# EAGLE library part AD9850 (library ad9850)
CMOS, 125 MHz Complete DDS Synthesizer
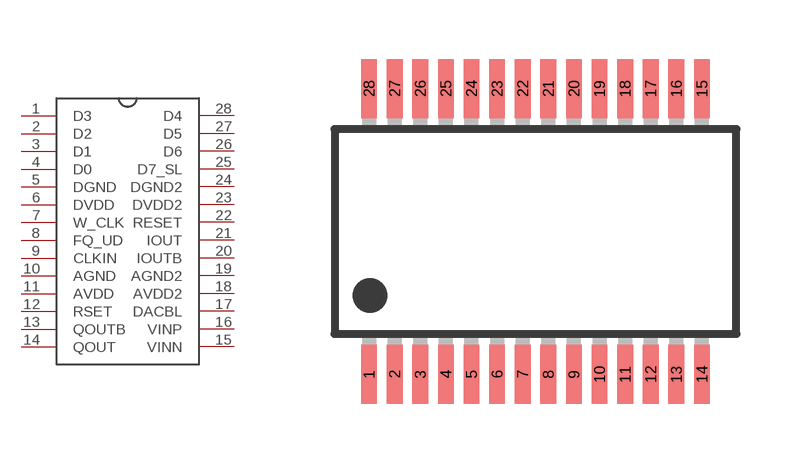
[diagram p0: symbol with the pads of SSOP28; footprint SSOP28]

Designator prefix -

## AD9850  [SSOP28]
1  D3  in
2  D2  in
3  D1  in
4  D0
5  DGND  sup
6  DVDD  sup
7  W_CLK
8  FQ_UD
9  CLKIN  in
10  AGND  sup
11  AVDD  sup
12  RSET  in
13  QOUTB  out
14  QOUT  out
15  VINN  in
16  VINP  in
17  DACBL  nc
18  AVDD2  sup
19  AGND2  sup
20  IOUTB  out
21  IOUT  out
22  RESET  in
23  DVDD2  sup
24  DGND2  sup
25  D7_SL  in
26  D6  in
27  D5  in
28  D4  in

## Footprint SSOP28 (pad centres in mm)
smd 0.4 x 1.5: 1 -4.225,-3.625; 2 -3.575,-3.625; 3 -2.925,-3.625; 4 -2.275,-3.625; 5 -1.625,-3.625; 6 -0.975,-3.625; 7 -0.325,-3.625; 8 0.325,-3.625; 9 0.975,-3.625; 10 1.625,-3.625; 11 2.275,-3.625; 12 2.925,-3.625; 13 3.575,-3.625; 14 4.225,-3.625; 15 4.225,3.625; 16 3.575,3.625; 17 2.925,3.625; 18 2.275,3.625; 19 1.625,3.625; 20 0.975,3.625; 21 0.325,3.625; 22 -0.325,3.625; 23 -0.975,3.625; 24 -1.625,3.625; 25 -2.275,3.625; 26 -2.925,3.625; 27 -3.575,3.625; 28 -4.225,3.625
